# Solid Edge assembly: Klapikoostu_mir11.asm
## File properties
Author: Türk
Template: Iso Assembly.asm
Last saved by: Türk
Revision: 3
Application: Solid Edge
Username: Türk
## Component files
Klapipuks.par
Klapi vedru_mir1.par
Klapp.par
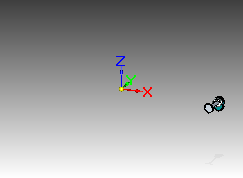
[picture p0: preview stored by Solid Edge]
